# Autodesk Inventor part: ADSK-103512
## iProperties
Shininess: 0.0
Created: 2000-11
Part Number: ADSK-103512
Description: Roller Chain 60 x 140" LONG
Document SubType Name: Modeling
Designer: gao
Stock Number: ADSK-103512
Density: 1 g/cm^3
Density: 0.0
Volumn: 0.0
Area: 0.0
PropertySet Name: Model Information
Control State: 0
Master: False
Checked Out: False
Author: gao
